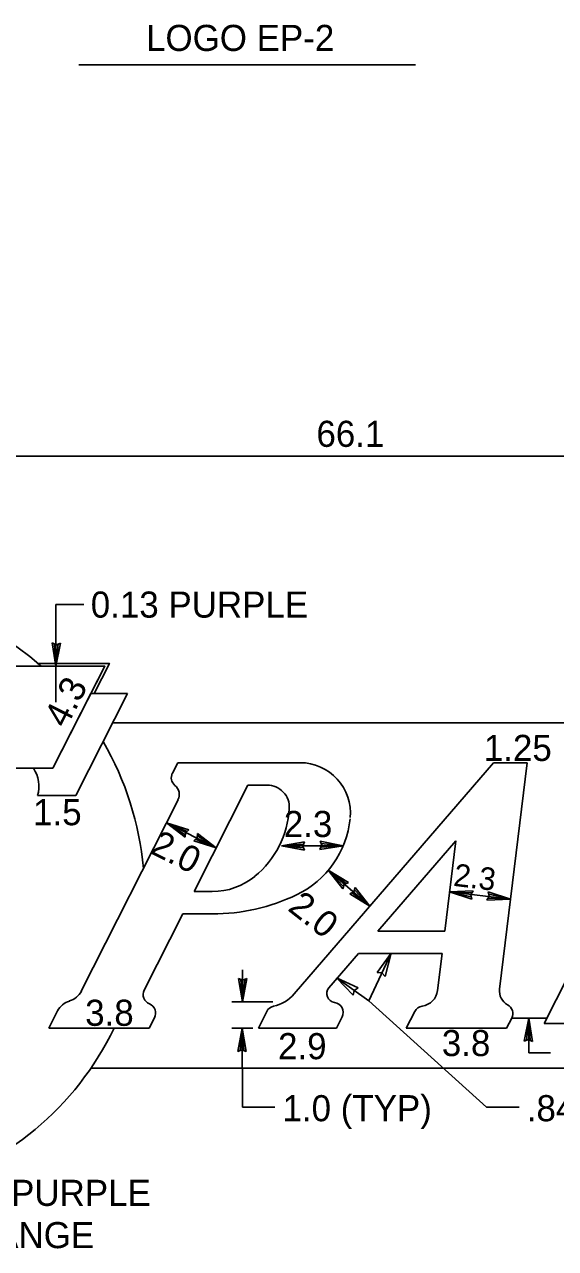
# Model space of a CAD drawing. Extents: x 10268197 to 10269179, y 2141503 to 2142677.
# Drawn here: x 10268484.78 to 10268499.02, y 2142084.36 to 2142117.17 of the extents above; entities that cross this region are included whole.
import ezdxf

# ---------------------------------------------------------------- set-up
doc = ezdxf.new("R2010")
doc.units = 0
for name, color, linetype in [('1', 7, 'Continuous'), ('20', 7, 'Continuous'), ('21', 7, 'Continuous'), ('3', 7, 'Continuous'), ('52', 7, 'Continuous')]:
    doc.layers.add(name, color=color, linetype=linetype)

msp = doc.modelspace()

# ---------------------------------------------------------------- linework, layer by layer
at = {"layer": '1'}
for p, q in [((10268486.932, 2142099.972), (10268478.307, 2142099.972)), ((10268487.056, 2142100.049), (10268485.138, 2142100.049)), ((10268486.932, 2142099.972), (10268485.539, 2142097.238)), ((10268487.056, 2142100.049), (10268486.645, 2142099.242)), ((10268486.56, 2142099.242), (10268485.539, 2142097.238)), ((10268486.151, 2142096.507), (10268487.544, 2142099.242)), ((10268487.544, 2142099.242), (10268486.151, 2142096.507)), ((10268487.544, 2142099.242), (10268486.56, 2142099.242)), ((10268487.544, 2142099.242), (10268486.56, 2142099.242)), ((10268487.142, 2142098.453), (10268516.747, 2142098.453)), ((10268484.499, 2142097.237), (10268485.539, 2142097.238)), ((10268485.539, 2142097.238), (10268485.019, 2142097.238)), ((10268488.885, 2142097.385), (10268488.742, 2142097.104)), ((10268492.169, 2142097.385), (10268488.885, 2142097.385)), ((10268492.011, 2142091.19), (10268497.355, 2142097.385)), ((10268498.254, 2142097.385), (10268497.355, 2142097.385)), ((10268498.254, 2142097.385), (10268497.514, 2142091.314)), ((10268490.77, 2142096.787), (10268489.326, 2142093.931)), ((10268491.281, 2142096.787), (10268490.77, 2142096.787)), ((10268486.151, 2142096.507), (10268485.128, 2142096.507)), ((10268485.128, 2142096.507), (10268486.151, 2142096.507)), ((10268488.894, 2142096.389), (10268486.301, 2142091.264)), ((10268494.247, 2142092.868), (10268496.34, 2142095.293)), ((10268496.34, 2142095.293), (10268496.046, 2142092.868)), ((10268489.814, 2142093.931), (10268489.326, 2142093.931)), ((10268489.024, 2142093.333), (10268487.99, 2142091.288)), ((10268489.814, 2142093.333), (10268489.024, 2142093.333)), ((10268496.046, 2142092.868), (10268494.247, 2142092.868)), ((10268492.94, 2142091.353), (10268493.731, 2142092.27)), ((10268495.973, 2142092.27), (10268493.731, 2142092.27)), ((10268495.973, 2142092.27), (10268495.852, 2142091.278)), ((10268498.713, 2142090.398), (10268499.663, 2142092.278)), ((10268485.665, 2142090.731), (10268485.431, 2142090.266)), ((10268491.048, 2142090.266), (10268491.275, 2142090.717)), ((10268495.012, 2142090.266), (10268495.241, 2142090.717)), ((10268488.123, 2142090.266), (10268488.264, 2142090.548)), ((10268493.296, 2142090.571), (10268493.141, 2142090.266)), ((10268497.841, 2142090.538), (10268497.704, 2142090.266)), ((10268499.348, 2142090.398), (10268498.713, 2142090.398)), ((10268488.123, 2142090.266), (10268485.431, 2142090.266)), ((10268493.141, 2142090.266), (10268491.048, 2142090.266)), ((10268495.012, 2142090.266), (10268497.704, 2142090.266)), ((10268486.559, 2142089.198), (10268512.032, 2142089.198))]:
    msp.add_line(p, q, dxfattribs=at)
for centre, radius, start, end in [((10268479.81, 2142093.833), 8.187, 48.5904, 218.8792), ((10268479.81, 2142093.833), 8.187, 5.051, 30.1953), ((10268484.287, 2142096.756), 0.877, 343.4611, 33.2756), ((10268484.287, 2142096.756), 0.877, 343.4611, 33.2756), ((10268492.169, 2142096.039), 1.346, 354.6609, 90), ((10268491.281, 2142096.189), 0.598, 356.6133, 90), ((10268489.34, 2142096.304), 2.542, 309.3947, 356.6133), ((10268490.977, 2142096.139), 2.542, 295.579, 354.2619), ((10268489.814, 2142095.726), 1.795, 270, 309.3947), ((10268489.814, 2142098.567), 5.235, 270, 295.579), ((10268493.121, 2142091.197), 0.239, 139.1995, 262.5416), ((10268488.23, 2142091.167), 0.269, 153.1708, 247.5682), ((10268495.377, 2142091.336), 0.479, 277.9506, 353.082), ((10268497.93, 2142091.263), 0.419, 173.0593, 241.464), ((10268488.025, 2142090.669), 0.269, 333.1431, 67.5682), ((10268493.055, 2142090.692), 0.269, 333.166, 82.5416), ((10268495.481, 2142090.596), 0.269, 97.9506, 153.1923), ((10268497.601, 2142090.659), 0.269, 333.284, 61.464), ((10268479.81, 2142093.833), 8.187, 237.0648, 334.1734)]:
    msp.add_arc(centre, radius, start, end, dxfattribs=at)
for centre, major_axis, start_param, end_param in [((10268488.975, 2142096.984), (0, -0.264), 4.240773, 5.605302), ((10268488.614, 2142096.532), (0, -0.316), 1.099604, 2.46371), ((10268485.836, 2142091.504), (0, -0.527), 0.286787, 1.099486), ((10268491.22, 2142091.884), (0, -1.055), 0.22194, 0.855152), ((10268486.132, 2142090.492), (0, -0.527), 3.428379, 4.240701), ((10268491.508, 2142090.598), (0, -0.264), 3.363532, 4.241567)]:
    msp.add_ellipse(centre, major_axis=major_axis, ratio=0.992614, start_param=start_param, end_param=end_param, dxfattribs=at)
at = {"layer": '20'}
for p, q in [((10268516.747, 2142105.604), (10268469.71, 2142105.604)), ((10268485.622, 2142100.048), (10268485.622, 2142101.63)), ((10268485.622, 2142101.63), (10268486.372, 2142101.63)), ((10268485.622, 2142099.012), (10268485.622, 2142099.972)), ((10268488.583, 2142095.776), (10268489.918, 2142095.101)), ((10268491.665, 2142095.161), (10268493.323, 2142095.161)), ((10268494.039, 2142093.542), (10268492.924, 2142094.504)), ((10268496.174, 2142093.924), (10268497.807, 2142093.726)), ((10268494.011, 2142091.001), (10268494.607, 2142092.278)), ((10268490.619, 2142090.978), (10268490.619, 2142091.836)), ((10268494.011, 2142091.001), (10268493.142, 2142091.618)), ((10268490.337, 2142090.978), (10268491.434, 2142090.978)), ((10268497.168, 2142088.155), (10268494.011, 2142091.001)), ((10268497.841, 2142090.538), (10268498.784, 2142090.538)), ((10268498.297, 2142089.609), (10268498.297, 2142090.538)), ((10268490.337, 2142090.266), (10268490.9, 2142090.266)), ((10268490.619, 2142088.155), (10268490.618, 2142090.266)), ((10268498.297, 2142089.609), (10268498.88, 2142089.609)), ((10268490.619, 2142088.155), (10268491.49, 2142088.155)), ((10268497.168, 2142088.155), (10268498.04, 2142088.155))]:
    msp.add_line(p, q, dxfattribs=at)
at = {"layer": '21'}
for p, q in [((10268486.233, 2142116.094), (10268495.258, 2142116.094)), ((10268485.622, 2142099.972), (10268485.523, 2142100.596)), ((10268485.632, 2142100.546), (10268485.523, 2142100.596)), ((10268485.622, 2142099.972), (10268485.58, 2142100.569)), ((10268485.622, 2142099.972), (10268485.742, 2142100.592)), ((10268485.622, 2142099.972), (10268485.684, 2142100.568)), ((10268485.742, 2142100.592), (10268485.632, 2142100.546)), ((10268488.583, 2142095.776), (10268489.185, 2142095.583)), ((10268488.583, 2142095.776), (10268489.082, 2142095.389)), ((10268488.583, 2142095.776), (10268489.087, 2142095.452)), ((10268488.583, 2142095.776), (10268489.135, 2142095.544)), ((10268489.082, 2142095.389), (10268489.091, 2142095.508)), ((10268489.091, 2142095.508), (10268489.185, 2142095.583)), ((10268489.41, 2142095.369), (10268489.317, 2142095.294)), ((10268489.918, 2142095.101), (10268489.317, 2142095.294)), ((10268489.918, 2142095.101), (10268489.366, 2142095.333)), ((10268489.419, 2142095.488), (10268489.41, 2142095.369)), ((10268489.918, 2142095.101), (10268489.414, 2142095.426)), ((10268489.918, 2142095.101), (10268489.419, 2142095.488)), ((10268493.323, 2142095.161), (10268492.704, 2142095.281)), ((10268492.704, 2142095.281), (10268492.749, 2142095.171)), ((10268491.665, 2142095.161), (10268492.288, 2142095.26)), ((10268491.665, 2142095.161), (10268492.262, 2142095.203)), ((10268491.665, 2142095.161), (10268492.284, 2142095.041)), ((10268491.665, 2142095.161), (10268492.261, 2142095.099)), ((10268492.239, 2142095.151), (10268492.288, 2142095.26)), ((10268492.284, 2142095.041), (10268492.239, 2142095.151)), ((10268492.749, 2142095.171), (10268492.699, 2142095.062)), ((10268493.323, 2142095.161), (10268492.699, 2142095.062)), ((10268493.323, 2142095.161), (10268492.726, 2142095.119)), ((10268493.323, 2142095.161), (10268492.727, 2142095.223)), ((10268492.924, 2142094.504), (10268493.461, 2142094.172)), ((10268492.924, 2142094.504), (10268493.315, 2142094.008)), ((10268492.924, 2142094.504), (10268493.334, 2142094.068)), ((10268492.924, 2142094.504), (10268493.403, 2142094.145)), ((10268493.315, 2142094.008), (10268493.352, 2142094.122)), ((10268493.352, 2142094.122), (10268493.461, 2142094.172)), ((10268493.648, 2142094.038), (10268493.611, 2142093.925)), ((10268494.039, 2142093.542), (10268493.628, 2142093.978)), ((10268494.039, 2142093.542), (10268493.648, 2142094.038)), ((10268493.611, 2142093.925), (10268493.502, 2142093.874)), ((10268494.039, 2142093.542), (10268493.502, 2142093.874)), ((10268494.039, 2142093.542), (10268493.559, 2142093.9)), ((10268496.174, 2142093.924), (10268496.805, 2142093.947)), ((10268496.174, 2142093.924), (10268496.775, 2142093.73)), ((10268496.174, 2142093.924), (10268496.758, 2142093.79)), ((10268496.174, 2142093.924), (10268496.772, 2142093.894)), ((10268496.743, 2142093.845), (10268496.805, 2142093.947)), ((10268496.775, 2142093.73), (10268496.743, 2142093.845)), ((10268497.238, 2142093.805), (10268497.176, 2142093.703)), ((10268497.807, 2142093.726), (10268497.176, 2142093.703)), ((10268497.807, 2142093.726), (10268497.206, 2142093.92)), ((10268497.206, 2142093.92), (10268497.238, 2142093.805)), ((10268497.807, 2142093.726), (10268497.209, 2142093.756)), ((10268497.807, 2142093.726), (10268497.223, 2142093.86)), ((10268490.619, 2142090.978), (10268490.52, 2142091.601)), ((10268490.629, 2142091.552), (10268490.52, 2142091.601)), ((10268490.619, 2142090.978), (10268490.577, 2142091.575)), ((10268490.619, 2142090.978), (10268490.739, 2142091.597)), ((10268490.619, 2142090.978), (10268490.681, 2142091.574)), ((10268490.739, 2142091.597), (10268490.629, 2142091.552)), ((10268498.297, 2142090.538), (10268498.177, 2142089.918)), ((10268498.297, 2142090.538), (10268498.235, 2142089.942)), ((10268498.297, 2142090.538), (10268498.396, 2142089.914)), ((10268498.297, 2142090.538), (10268498.339, 2142089.94)), ((10268490.618, 2142090.266), (10268490.498, 2142089.646)), ((10268490.618, 2142090.266), (10268490.556, 2142089.67)), ((10268490.618, 2142090.266), (10268490.718, 2142089.642)), ((10268490.618, 2142090.266), (10268490.66, 2142089.669)), ((10268490.498, 2142089.646), (10268490.609, 2142089.692)), ((10268490.609, 2142089.692), (10268490.718, 2142089.642)), ((10268498.177, 2142089.918), (10268498.287, 2142089.963)), ((10268498.287, 2142089.963), (10268498.396, 2142089.914))]:
    msp.add_line(p, q, dxfattribs=at)
at = {"layer": '3'}
msp.add_lwpolyline([(10268485.138, 2142100.049), (10268487.056, 2142100.049), (10268486.645, 2142099.242), (10268486.56, 2142099.242), (10268486.932, 2142099.972), (10268485.225, 2142099.973)], close=True, dxfattribs=at)
at = {"layer": '52'}
for p, q in [((10268494.607, 2142092.278), (10268494.23, 2142091.758)), ((10268494.447, 2142091.656), (10268494.607, 2142092.278)), ((10268494.23, 2142091.758), (10268494.36, 2142091.749)), ((10268494.36, 2142091.749), (10268494.447, 2142091.656)), ((10268493.142, 2142091.618), (10268493.586, 2142091.153)), ((10268493.725, 2142091.349), (10268493.142, 2142091.618)), ((10268493.618, 2142091.281), (10268493.725, 2142091.349)), ((10268493.586, 2142091.153), (10268493.618, 2142091.281))]:
    msp.add_line(p, q, dxfattribs=at)

# ---------------------------------------------------------------- texts
at = {"layer": '1'}
msp.add_text('LOGO EP-2', height=0.7, dxfattribs=at).set_placement((10268488.037, 2142116.464))
at = {"layer": '20'}
for s, p in [('66.1', (10268492.605, 2142105.852)), ('0.13 PURPLE', (10268486.555, 2142101.274)), ('1.25', (10268497.093, 2142097.432)), ('1.5', (10268485.009, 2142095.709)), ('2.3', (10268491.73, 2142095.393)), ('3.8', (10268486.405, 2142090.332)), ('2.9', (10268491.576, 2142089.437)), ('3.8', (10268495.967, 2142089.52)), ('1.0 (TYP)', (10268491.695, 2142087.774)), ('.84 (TYP)', (10268498.244, 2142087.774)), ('PURPLE', (10268484.419, 2142085.505)), ('ORANGE', (10268482.589, 2142084.372))]:
    msp.add_text(s, height=0.7, dxfattribs=at).set_placement(p)
for s, height, rotation, p in [('4.3', 0.7, 63.001, (10268485.895, 2142098.284)), ('2.0', 0.7, 333.1665, (10268488.108, 2142094.98)), ('2.3', 0.6037, 353.0765, (10268496.26, 2142094.086)), ('2.0', 0.7, 321.8741, (10268491.807, 2142093.445))]:
    msp.add_text(s, height=height, rotation=rotation, dxfattribs=at).set_placement(p)

doc.saveas('drawing.dxf')
